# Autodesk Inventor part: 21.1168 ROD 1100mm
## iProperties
Created: 2011-02
Part Number: 21.1168 ROD 1100mm
Document SubType Name: Modeling
Designer: Administrator
Density: 7.85 g/cm^3
Material: Steel
Mass: 432.833 g
Surface Area: 277.827 cm^2
Volume: 55.138 cm^3
Author: Administrator
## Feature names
1. Sweep1
2. Extrusion2
3. Extrusion3
